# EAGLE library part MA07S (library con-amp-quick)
AMP QUICK CONNECTOR
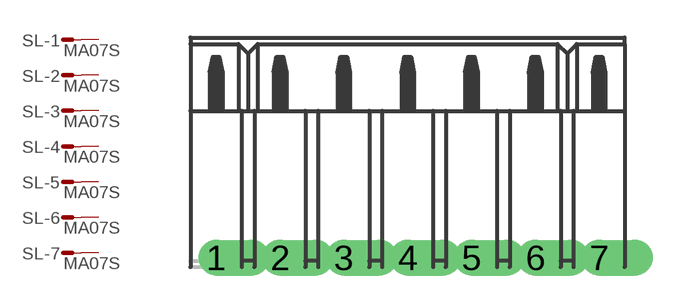
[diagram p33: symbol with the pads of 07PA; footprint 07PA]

Designator prefix SL; gates -1=M -2=M -3=M -4=M -5=M -6=M -7=M

## MA07S  [07PA]
1  -1:S  pas
2  -2:S  pas
3  -3:S  pas
4  -4:S  pas
5  -5:S  pas
6  -6:S  pas
7  -7:S  pas

## Footprint 07PA (pad centres in mm)
AMP QUICK CONNECTOR
drill 0.914 offset: 1 -7.62,0; 2 -5.08,0; 3 -2.54,0; 4 0,0; 5 2.54,0; 6 5.08,0; 7 7.62,0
